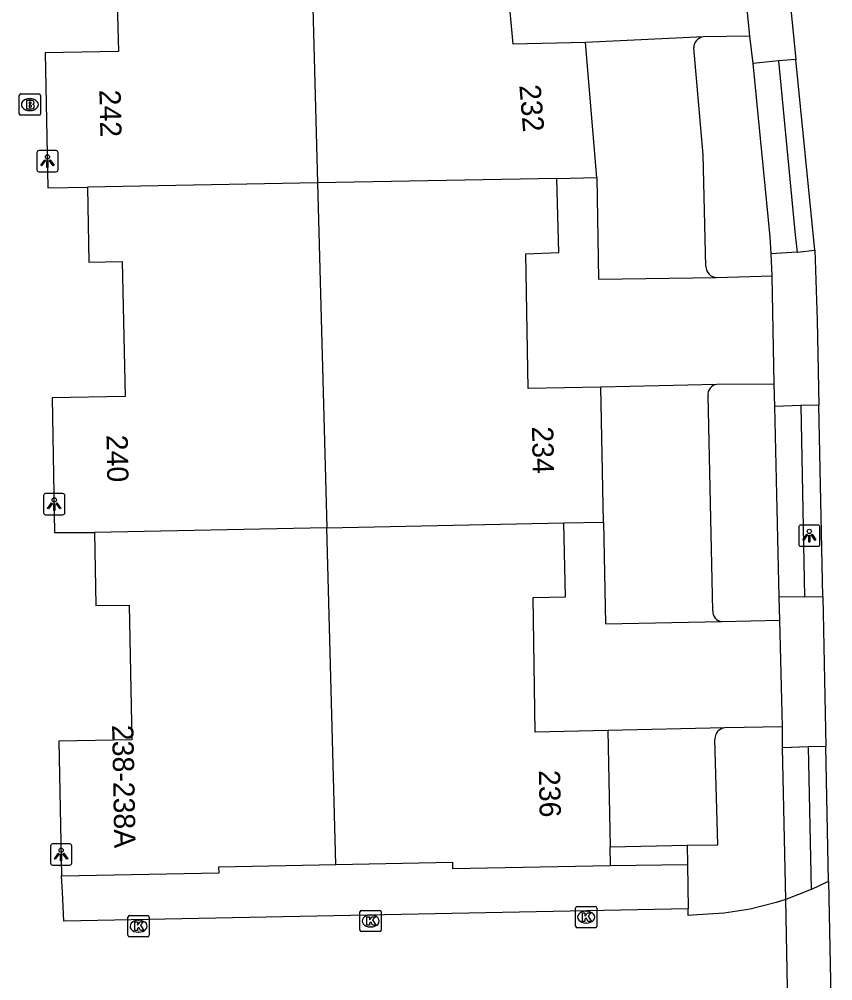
# Model space of a CAD drawing. Extents: x 161389 to 162585, y 388479 to 389761.
# Drawn here: x 162452.88 to 162491.16, y 389013.71 to 389058.96 of the extents above; entities that cross this region are included whole.
import ezdxf

# ---------------------------------------------------------------- set-up
doc = ezdxf.new("R2010")
doc.units = 0
for name, color, linetype in [('IMGEO_Brandkraan', 7, 'Continuous'), ('IMGEO_Kolk', 7, 'Continuous'), ('IMGEO_Lichtpunt', 7, 'Continuous'), ('IMGEO_Pand', 7, 'Continuous'), ('IMGEO_Pand_nummerreeks', 7, 'Continuous'), ('IMGEO_Parkeervlak_open', 7, 'Continuous'), ('IMGEO_Rijbaan_lokaal_gesloten', 7, 'Continuous'), ('IMGEO_Rijbaan_lokaal_open', 7, 'Continuous'), ('IMGEO_Voetpad_open', 7, 'Continuous')]:
    doc.layers.add(name, color=color, linetype=linetype)

msp = doc.modelspace()

# ---------------------------------------------------------------- linework, layer by layer
at = {"layer": 'IMGEO_Brandkraan'}
for p, q in [((162452.951, 389055.445), (162453.803, 389055.445)), ((162452.876, 389054.519), (162452.876, 389055.371)), ((162453.364, 389055.225), (162453.389, 389055.225)), ((162453.877, 389055.371), (162453.877, 389054.519)), ((162453.387, 389054.665), (162453.362, 389054.665)), ((162453.803, 389054.445), (162452.951, 389054.445))]:
    msp.add_line(p, q, dxfattribs=at)
for points in [[(162452.951, 389055.445), (162453.803, 389055.445)], [(162452.876, 389054.519), (162452.876, 389055.371)], [(162453.224, 389055.145), (162453.224, 389054.745), (162453.437, 389054.745)], [(162453.455, 389055.145), (162453.224, 389055.145)], [(162453.403, 389055.064), (162453.349, 389055.064), (162453.349, 389054.988)], [(162453.349, 389054.988), (162453.402, 389054.988)], [(162453.877, 389055.371), (162453.877, 389054.519)], [(162453.411, 389054.912), (162453.349, 389054.912), (162453.349, 389054.831)], [(162453.349, 389054.831), (162453.411, 389054.831)], [(162453.803, 389054.445), (162452.951, 389054.445)]]:
    msp.add_lwpolyline(points, dxfattribs=at)
for centre, radius, start, end in [((162452.953, 389055.369), 0.0765, 91.552, 178.448), ((162452.953, 389055.369), 0.0765, 91.552, 178.448), ((162453.801, 389055.369), 0.0765, 1.552, 88.448), ((162453.801, 389055.369), 0.0765, 1.552, 88.448), ((162453.404, 389055.026), 0.0379, 267.8285, 90.9355), ((162453.459, 389055), 0.145, 59.4692, 91.5367), ((162453.484, 389055.047), 0.0922, 285.5137, 58.1501), ((162452.953, 389054.521), 0.0765, 181.552, 268.448), ((162452.953, 389054.521), 0.0765, 181.552, 268.448), ((162453.412, 389054.871), 0.0404, 269.8759, 90.5077), ((162453.443, 389054.996), 0.251, 268.6676, 293.5347), ((162453.489, 389054.855), 0.105, 301.3115, 78.989), ((162453.801, 389054.521), 0.0765, 271.552, 358.448), ((162453.801, 389054.521), 0.0765, 271.552, 358.448)]:
    msp.add_arc(centre, radius, start, end, dxfattribs=at)
for centre, major_axis, ratio, start_param, end_param in [((162453.363, 389054.945), (-0.387, 0.002), 0.722429, 4.712389, 7.853982), ((162453.388, 389054.945), (-0.39, 0.002), 0.717154, 1.570796, 4.712389)]:
    msp.add_ellipse(centre, major_axis=major_axis, ratio=ratio, start_param=start_param, end_param=end_param, dxfattribs=at)
at = {"layer": 'IMGEO_Kolk'}
for p, q in [((162468.984, 389017.026), (162469.836, 389017.026)), ((162479.052, 389016.283), (162479.052, 389017.135)), ((162479.127, 389017.209), (162479.979, 389017.209)), ((162479.54, 389016.989), (162479.565, 389016.989)), ((162480.053, 389017.135), (162480.053, 389016.283)), ((162457.991, 389015.854), (162457.991, 389016.706)), ((162458.066, 389016.78), (162458.918, 389016.78)), ((162458.479, 389016.56), (162458.504, 389016.56)), ((162458.992, 389016.706), (162458.992, 389015.854)), ((162468.909, 389016.1), (162468.909, 389016.952)), ((162469.397, 389016.806), (162469.422, 389016.806)), ((162469.91, 389016.952), (162469.91, 389016.1)), ((162469.42, 389016.246), (162469.395, 389016.246)), ((162479.979, 389016.209), (162479.127, 389016.209)), ((162479.563, 389016.429), (162479.538, 389016.429)), ((162458.918, 389015.78), (162458.066, 389015.78)), ((162458.502, 389016), (162458.477, 389016)), ((162469.836, 389016.026), (162468.984, 389016.026))]:
    msp.add_line(p, q, dxfattribs=at)
for points in [[(162468.984, 389017.026), (162469.836, 389017.026)], [(162479.052, 389016.283), (162479.052, 389017.135)], [(162479.127, 389017.209), (162479.979, 389017.209)], [(162480.053, 389017.135), (162480.053, 389016.283)], [(162457.991, 389015.854), (162457.991, 389016.706)], [(162458.066, 389016.78), (162458.918, 389016.78)], [(162458.992, 389016.706), (162458.992, 389015.854)], [(162468.909, 389016.1), (162468.909, 389016.952)], [(162469.23, 389016.726), (162469.353, 389016.726), (162469.353, 389016.575), (162469.483, 389016.726), (162469.647, 389016.726), (162469.501, 389016.575), (162469.654, 389016.326), (162469.502, 389016.326), (162469.417, 389016.49), (162469.353, 389016.423), (162469.353, 389016.326), (162469.23, 389016.326), (162469.23, 389016.726)], [(162469.91, 389016.952), (162469.91, 389016.1)], [(162479.373, 389016.909), (162479.496, 389016.909), (162479.496, 389016.758), (162479.626, 389016.909), (162479.79, 389016.909), (162479.644, 389016.758), (162479.797, 389016.509), (162479.645, 389016.509), (162479.56, 389016.673), (162479.496, 389016.606), (162479.496, 389016.509), (162479.373, 389016.509), (162479.373, 389016.909)], [(162458.312, 389016.48), (162458.435, 389016.48), (162458.435, 389016.329), (162458.565, 389016.48), (162458.729, 389016.48), (162458.583, 389016.329), (162458.736, 389016.08), (162458.584, 389016.08), (162458.499, 389016.244), (162458.435, 389016.177), (162458.435, 389016.08), (162458.312, 389016.08), (162458.312, 389016.48)], [(162479.979, 389016.209), (162479.127, 389016.209)], [(162458.918, 389015.78), (162458.066, 389015.78)], [(162469.836, 389016.026), (162468.984, 389016.026)]]:
    msp.add_lwpolyline(points, dxfattribs=at)
for centre, start, end in [((162468.986, 389016.95), 91.552, 178.448), ((162468.986, 389016.95), 91.552, 178.448), ((162469.834, 389016.95), 1.552, 88.448), ((162469.834, 389016.95), 1.552, 88.448), ((162479.129, 389017.133), 91.552, 178.448), ((162479.129, 389017.133), 91.552, 178.448), ((162479.977, 389017.133), 1.552, 88.448), ((162479.977, 389017.133), 1.552, 88.448), ((162458.068, 389016.704), 91.552, 178.448), ((162458.068, 389016.704), 91.552, 178.448), ((162458.916, 389016.704), 1.552, 88.448), ((162458.916, 389016.704), 1.552, 88.448), ((162468.986, 389016.102), 181.552, 268.448), ((162468.986, 389016.102), 181.552, 268.448), ((162469.834, 389016.102), 271.552, 358.448), ((162469.834, 389016.102), 271.552, 358.448), ((162479.129, 389016.285), 181.552, 268.448), ((162479.129, 389016.285), 181.552, 268.448), ((162479.977, 389016.285), 271.552, 358.448), ((162479.977, 389016.285), 271.552, 358.448), ((162458.068, 389015.856), 181.552, 268.448), ((162458.068, 389015.856), 181.552, 268.448), ((162458.916, 389015.856), 271.552, 358.448), ((162458.916, 389015.856), 271.552, 358.448)]:
    msp.add_arc(centre, 0.0765, start, end, dxfattribs=at)
for centre, major_axis, ratio, start_param, end_param in [((162479.539, 389016.709), (-0.387, 0.002), 0.722429, 4.712389, 7.853982), ((162479.564, 389016.709), (-0.39, 0.002), 0.717154, 1.570796, 4.712389), ((162458.478, 389016.28), (-0.387, 0.002), 0.722429, 4.712389, 7.853982), ((162458.503, 389016.28), (-0.39, 0.002), 0.717154, 1.570796, 4.712389), ((162469.396, 389016.526), (-0.387, 0.002), 0.722429, 4.712389, 7.853982), ((162469.421, 389016.526), (-0.39, 0.002), 0.717154, 1.570796, 4.712389)]:
    msp.add_ellipse(centre, major_axis=major_axis, ratio=ratio, start_param=start_param, end_param=end_param, dxfattribs=at)
at = {"layer": 'IMGEO_Lichtpunt'}
for p, q in [((162454.608, 389052.785), (162453.8, 389052.785)), ((162454.608, 389052.785), (162453.8, 389052.785)), ((162453.706, 389052.69), (162453.706, 389051.883)), ((162453.706, 389052.69), (162453.706, 389051.883)), ((162454.702, 389051.883), (162454.702, 389052.69)), ((162454.702, 389051.883), (162454.702, 389052.69)), ((162453.8, 389051.789), (162454.608, 389051.789)), ((162453.8, 389051.789), (162454.608, 389051.789)), ((162454.026, 389036.545), (162454.026, 389035.738)), ((162454.026, 389036.545), (162454.026, 389035.738)), ((162454.928, 389036.64), (162454.12, 389036.64)), ((162454.928, 389036.64), (162454.12, 389036.64)), ((162455.022, 389035.738), (162455.022, 389036.545)), ((162455.022, 389035.738), (162455.022, 389036.545)), ((162454.12, 389035.644), (162454.928, 389035.644)), ((162454.12, 389035.644), (162454.928, 389035.644)), ((162489.556, 389035.061), (162489.556, 389034.254)), ((162489.556, 389035.061), (162489.556, 389034.254)), ((162490.458, 389035.156), (162489.65, 389035.156)), ((162490.458, 389035.156), (162489.65, 389035.156)), ((162490.552, 389034.254), (162490.552, 389035.061)), ((162490.552, 389034.254), (162490.552, 389035.061)), ((162489.65, 389034.16), (162490.458, 389034.16)), ((162489.65, 389034.16), (162490.458, 389034.16)), ((162455.251, 389020.153), (162454.443, 389020.153)), ((162455.251, 389020.153), (162454.443, 389020.153)), ((162454.349, 389020.058), (162454.349, 389019.251)), ((162454.349, 389020.058), (162454.349, 389019.251)), ((162455.345, 389019.251), (162455.345, 389020.058)), ((162455.345, 389019.251), (162455.345, 389020.058)), ((162454.443, 389019.157), (162455.251, 389019.157)), ((162454.443, 389019.157), (162455.251, 389019.157))]:
    msp.add_line(p, q, dxfattribs=at)
for points in [[(162454.08, 389052.354), (162454.119, 389052.326), (162453.931, 389052.064), (162453.893, 389052.091), (162454.08, 389052.354)], [(162454.182, 389052.306), (162454.229, 389052.306), (162454.229, 389051.984), (162454.182, 389051.984), (162454.182, 389052.306)], [(162454.292, 389052.326), (162454.33, 389052.353), (162454.517, 389052.091), (162454.478, 389052.063), (162454.292, 389052.326)], [(162454.4, 389036.209), (162454.439, 389036.181), (162454.251, 389035.919), (162454.213, 389035.946), (162454.4, 389036.209)], [(162454.502, 389036.161), (162454.549, 389036.161), (162454.549, 389035.839), (162454.502, 389035.839), (162454.502, 389036.161)], [(162454.612, 389036.181), (162454.65, 389036.208), (162454.837, 389035.946), (162454.798, 389035.918), (162454.612, 389036.181)], [(162489.93, 389034.725), (162489.969, 389034.697), (162489.781, 389034.435), (162489.743, 389034.462), (162489.93, 389034.725)], [(162490.032, 389034.677), (162490.079, 389034.677), (162490.079, 389034.355), (162490.032, 389034.355), (162490.032, 389034.677)], [(162490.142, 389034.697), (162490.18, 389034.724), (162490.367, 389034.462), (162490.328, 389034.434), (162490.142, 389034.697)], [(162454.723, 389019.722), (162454.762, 389019.694), (162454.574, 389019.432), (162454.536, 389019.459), (162454.723, 389019.722)], [(162454.825, 389019.674), (162454.872, 389019.674), (162454.872, 389019.352), (162454.825, 389019.352), (162454.825, 389019.674)], [(162454.935, 389019.694), (162454.973, 389019.721), (162455.16, 389019.459), (162455.121, 389019.431), (162454.935, 389019.694)]]:
    msp.add_lwpolyline(points, dxfattribs=at)
for centre in [(162454.205, 389052.488), (162454.525, 389036.343), (162490.055, 389034.859), (162454.848, 389019.856)]:
    msp.add_circle(centre, 0.0994, dxfattribs=at)
for centre, start, end in [((162453.8, 389052.69), 90, 180), ((162453.8, 389052.69), 90, 180), ((162454.608, 389052.69), 0, 90), ((162454.608, 389052.69), 0, 90), ((162453.8, 389051.883), 180, 270), ((162453.8, 389051.883), 180, 270), ((162454.608, 389051.883), 270, 0), ((162454.608, 389051.883), 270, 360), ((162454.12, 389036.545), 90, 180), ((162454.12, 389036.545), 90, 180), ((162454.928, 389036.545), 0, 90), ((162454.928, 389036.545), 0, 90), ((162454.12, 389035.738), 180, 270), ((162454.12, 389035.738), 180, 270), ((162454.928, 389035.738), 270, 0), ((162454.928, 389035.738), 270, 360), ((162489.65, 389035.061), 90, 180), ((162489.65, 389035.061), 90, 180), ((162490.458, 389035.061), 0, 90), ((162490.458, 389035.061), 0, 90), ((162489.65, 389034.254), 180, 270), ((162489.65, 389034.254), 180, 270), ((162490.458, 389034.254), 270, 0), ((162490.458, 389034.254), 270, 360), ((162454.443, 389020.058), 90, 180), ((162454.443, 389020.058), 90, 180), ((162455.251, 389020.058), 0, 90), ((162455.251, 389020.058), 0, 90), ((162454.443, 389019.251), 180, 270), ((162454.443, 389019.251), 180, 270), ((162455.251, 389019.251), 270, 0), ((162455.251, 389019.251), 270, 360)]:
    msp.add_arc(centre, 0.0946, start, end, dxfattribs=at)
at = {"layer": 'IMGEO_Pand'}
for points in [[(162466.451, 389068.325), (162466.908, 389051.26)], [(162479.527, 389057.87), (162476.112, 389057.792), (162475.543, 389064.108), (162477.087, 389064.248), (162476.711, 389068.399)], [(162455.829, 389063.752), (162457.378, 389063.782), (162457.541, 389057.449), (162454.089, 389057.375), (162454.226, 389051.027), (162456.088, 389051.063)], [(162480.056, 389051.518), (162479.527, 389057.87)], [(162478.18, 389051.466), (162466.908, 389051.26)], [(162480.247, 389041.656), (162476.818, 389041.591), (162476.719, 389047.929), (162478.271, 389047.984), (162478.18, 389051.466)], [(162478.18, 389051.466), (162480.056, 389051.518)], [(162456.088, 389051.063), (162456.148, 389047.533), (162457.718, 389047.56), (162457.857, 389041.216), (162454.427, 389041.153), (162454.543, 389034.802), (162456.411, 389034.814)], [(162466.908, 389051.26), (162456.088, 389051.063)], [(162466.908, 389051.26), (162467.343, 389035.034)], [(162480.369, 389035.3), (162480.247, 389041.656)], [(162467.343, 389035.034), (162478.509, 389035.258)], [(162480.565, 389025.486), (162477.152, 389025.415), (162477.055, 389031.754), (162478.582, 389031.779), (162478.509, 389035.258)], [(162478.509, 389035.258), (162480.369, 389035.3)], [(162456.411, 389034.814), (162456.474, 389031.368), (162458.044, 389031.397), (162458.169, 389025.059), (162454.739, 389024.994), (162454.866, 389018.655)], [(162467.343, 389035.034), (162456.411, 389034.814)], [(162467.768, 389019.184), (162467.343, 389035.034)], [(162480.565, 389025.486), (162480.679, 389020.017)], [(162480.697, 389019.139), (162480.679, 389020.017)], [(162467.768, 389019.184), (162473.26, 389019.295), (162473.267, 389019.005), (162480.697, 389019.139)], [(162454.866, 389018.655), (162462.278, 389018.795), (162462.276, 389019.072), (162467.768, 389019.184)]]:
    msp.add_lwpolyline(points, dxfattribs=at)
at = {"layer": 'IMGEO_Parkeervlak_open'}
for points in [[(162485.191, 389047.326), (162485.065, 389052.589), (162484.618, 389057.616)], [(162485.509, 389031.116), (162485.287, 389041.259)], [(162484.31, 389020.088), (162485.749, 389020.116), (162485.614, 389025.087)], [(162484.323, 389019.178), (162484.353, 389017.102)]]:
    msp.add_lwpolyline(points, dxfattribs=at)
for centre, radius, start, end in [((162485.114, 389057.637), 0.496, 94.6059, 182.4587), ((162485.714, 389047.33), 0.523, 180.3959, 266.8924), ((162485.742, 389041.317), 0.459, 95.2554, 187.2895), ((162485.98, 389031.087), 0.472, 176.47, 265.5765), ((162486.104, 389025.122), 0.491, 93.7233, 184.0751)]:
    msp.add_arc(centre, radius, start, end, dxfattribs=at)
at = {"layer": 'IMGEO_Rijbaan_lokaal_gesloten'}
for points in [[(162488.727, 389064.009), (162489.416, 389057.074)], [(162490.306, 389048.101), (162489.416, 389057.074)], [(162490.306, 389048.101), (162490.42, 389044.795), (162490.5, 389040.809)], [(162490.682, 389031.792), (162490.5, 389040.809)], [(162490.682, 389031.792), (162490.824, 389024.737)], [(162490.951, 389018.401), (162490.824, 389024.737)], [(162490.951, 389018.401), (162491.156, 389008.259)]]:
    msp.add_lwpolyline(points, dxfattribs=at)
at = {"layer": 'IMGEO_Rijbaan_lokaal_open'}
for points in [[(162487.26, 389058.173), (162486.757, 389063.235)], [(162485.074, 389058.132), (162479.527, 389057.87)], [(162487.26, 389058.173), (162485.074, 389058.132)], [(162480.056, 389051.518), (162480.131, 389046.728), (162485.686, 389046.807)], [(162485.686, 389046.807), (162488.298, 389046.888)], [(162488.4, 389041.797), (162488.298, 389046.888)], [(162485.7, 389041.774), (162480.247, 389041.656)], [(162488.4, 389041.797), (162485.7, 389041.774)], [(162480.369, 389035.3), (162480.461, 389030.518), (162485.944, 389030.616)], [(162485.944, 389030.616), (162488.661, 389030.685)], [(162488.794, 389025.661), (162488.661, 389030.685)], [(162486.072, 389025.612), (162480.565, 389025.486)], [(162488.794, 389025.661), (162486.072, 389025.612)], [(162484.353, 389017.102), (162454.974, 389016.52), (162454.905, 389017.876), (162454.866, 389018.655)], [(162488.94, 389017.541), (162488.487, 389017.396), (162487.275, 389017.091), (162486.041, 389016.896), (162484.794, 389016.811), (162484.357, 389016.793), (162484.353, 389017.102)], [(162489.105, 389009.202), (162488.94, 389017.541)]]:
    msp.add_lwpolyline(points, dxfattribs=at)
at = {"layer": 'IMGEO_Voetpad_open'}
for points in [[(162487.417, 389056.887), (162487.26, 389058.173)], [(162488.599, 389056.999), (162487.417, 389056.887)], [(162488.264, 389047.918), (162488.211, 389048.717), (162487.417, 389056.887)], [(162489.416, 389057.074), (162488.599, 389056.999)], [(162488.599, 389056.999), (162489.393, 389048.816), (162489.477, 389048.003)], [(162489.477, 389048.003), (162488.264, 389047.918)], [(162488.298, 389046.888), (162488.264, 389047.918)], [(162489.477, 389048.003), (162490.306, 389048.101)], [(162488.435, 389040.733), (162488.4, 389041.797)], [(162489.652, 389040.784), (162488.435, 389040.733)], [(162488.632, 389031.766), (162488.435, 389040.733)], [(162490.5, 389040.809), (162489.652, 389040.784)], [(162489.652, 389040.784), (162489.83, 389031.789)], [(162489.83, 389031.789), (162488.632, 389031.766)], [(162488.661, 389030.685), (162488.632, 389031.766)], [(162489.83, 389031.789), (162490.682, 389031.792)], [(162488.79, 389024.68), (162488.794, 389025.661)], [(162489.992, 389024.729), (162488.79, 389024.68)], [(162488.94, 389017.541), (162488.79, 389024.68)], [(162490.824, 389024.737), (162489.992, 389024.729)], [(162489.992, 389024.729), (162490.144, 389018.011)], [(162480.679, 389020.017), (162484.31, 389020.088)], [(162484.31, 389020.088), (162484.323, 389019.178)], [(162480.697, 389019.139), (162484.323, 389019.178)], [(162490.144, 389018.011), (162490.951, 389018.401)], [(162490.144, 389018.011), (162488.94, 389017.541)]]:
    msp.add_lwpolyline(points, dxfattribs=at)

# ---------------------------------------------------------------- texts
at = {"layer": 'IMGEO_Pand_nummerreeks'}
for s, rotation, p in [('242', 271.2363, (162456.647, 389055.637)), ('232', 274.7409, (162476.405, 389055.849)), ('234', 271.0996, (162477.002, 389039.793)), ('240', 271.0464, (162456.98, 389039.399)), ('238-238A', 271.1026, (162457.244, 389025.747)), ('236', 271.1914, (162477.323, 389023.623))]:
    msp.add_text(s, height=1, rotation=rotation, dxfattribs=at).set_placement(p)

doc.saveas('drawing.dxf')
